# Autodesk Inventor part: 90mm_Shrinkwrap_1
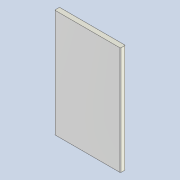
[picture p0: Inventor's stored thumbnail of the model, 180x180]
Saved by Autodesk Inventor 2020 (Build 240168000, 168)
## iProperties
Created: 2020-11
Part Number: 90mm_Shrinkwrap_1
Material: Generic
Document SubType Name: Modeling
Designer: Yolande
Density: 1 g/cm^3
Appearance: Default
Author: Yolande
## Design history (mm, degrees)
derived "90mm.iam"
body "Solid1"
node "Lambdaboard 90mm Mineral White.ipt:1" dims "d0" = 10
